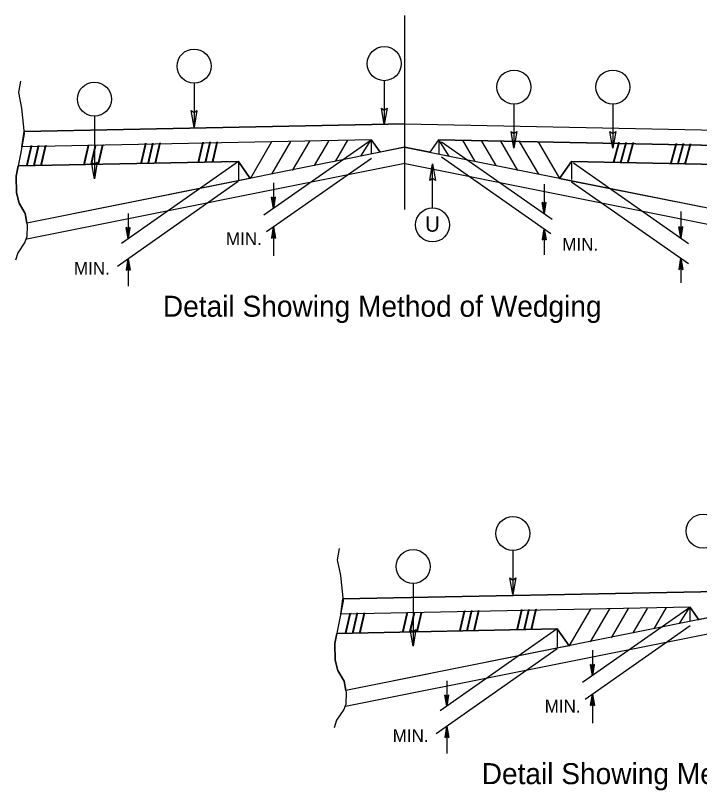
# Model space of a CAD drawing. Extents: x 1818040 to 1825768, y 638918 to 648046.
# Drawn here: x 1824035 to 1824618, y 640342 to 641002 of the extents above; entities that cross this region are included whole.
import ezdxf

# ---------------------------------------------------------------- set-up
doc = ezdxf.new("R2010")
doc.units = 0
for name, color, linetype in [('Typical Detail Wedge2 CELL', 7, 'Continuous'), ('Typical ID Circle CELL', 7, 'Continuous'), ('Typical Terminator CELL', 7, 'Continuous'), ('Typical Text General CELL', 7, 'Continuous'), ('Typical Text ID Circle CELL', 7, 'Continuous')]:
    doc.layers.add(name, color=color, linetype=linetype)

msp = doc.modelspace()

# ---------------------------------------------------------------- linework, layer by layer
at = {"layer": 'Typical Detail Wedge2 CELL'}
for p, q in [((1824367.23, 640836.88), (1824367.23, 641002.31)), ((1824367.23, 640836.88), (1824367.23, 640949.86)), ((1824367.22, 640909.96), (1824042.56, 640903.48)), ((1824042.56, 640903.48), (1824367.22, 640909.96)), ((1824367.22, 640909.96), (1824691.9, 640903.48)), ((1824367.25, 640909.96), (1824691.9, 640903.48)), ((1824040.71, 640890.43), (1824042.56, 640903.48)), ((1824338.74, 640896.39), (1824040.71, 640890.43)), ((1824338.74, 640896.39), (1824040.71, 640890.43)), ((1824253.59, 640894.68), (1824235.14, 640863.07)), ((1824338.37, 640896.15), (1824246.9, 640832.08)), ((1824269.79, 640895.02), (1824253.46, 640866.98)), ((1824285.83, 640895.33), (1824271.17, 640870.2)), ((1824301.99, 640895.29), (1824289.84, 640874.49)), ((1824318.28, 640896.13), (1824307.7, 640877.97)), ((1824329.51, 640882.51), (1824338.32, 640896.27)), ((1824338.32, 640896.27), (1824338.32, 640884.96)), ((1824346.03, 640885.7), (1824338.74, 640896.39)), ((1824338.74, 640896.04), (1824346.03, 640885.7)), ((1824395.95, 640896.39), (1824388.42, 640885.7)), ((1824395.95, 640896.39), (1824388.42, 640885.7)), ((1824395.47, 640896.15), (1824395.93, 640896.13)), ((1824395.95, 640896.39), (1824693.76, 640890.43)), ((1824693.76, 640890.43), (1824395.95, 640896.39)), ((1824404.95, 640882.51), (1824396.14, 640896.27)), ((1824396.14, 640896.27), (1824396.14, 640883.81)), ((1824398.43, 640894.66), (1824492.67, 640828.66)), ((1824416.17, 640896.13), (1824426.76, 640877.97)), ((1824432.46, 640895.29), (1824444.61, 640874.49)), ((1824448.62, 640895.33), (1824463.29, 640870.2)), ((1824464.66, 640895.02), (1824481, 640866.98)), ((1824480.88, 640894.68), (1824499.05, 640863.53)), ((1824367.71, 640890), (1824044.99, 640825.45)), ((1824366.74, 640890), (1824346.03, 640885.7)), ((1824366.74, 640890), (1824689.47, 640825.45)), ((1824388.42, 640885.7), (1824366.74, 640890)), ((1824338.58, 640880.49), (1824249.07, 640817.82)), ((1824398.3, 640881.83), (1824491.62, 640816.49)), ((1824225.2, 640877.84), (1824037.55, 640874.08)), ((1824037.55, 640874.08), (1824225.2, 640877.84)), ((1824367.1, 640876.11), (1824044.89, 640811.66)), ((1824225.2, 640877.84), (1824125.56, 640808.07)), ((1824235.4, 640863.5), (1824225.2, 640877.84)), ((1824225.2, 640877.84), (1824225.2, 640861.47)), ((1824225.2, 640877.84), (1824235.38, 640863.53)), ((1824367.35, 640876.11), (1824690.31, 640811.51)), ((1824509.25, 640877.84), (1824499.05, 640863.53)), ((1824499.07, 640863.53), (1824509.25, 640877.84)), ((1824509.25, 640877.84), (1824696.91, 640874.08)), ((1824509.25, 640877.84), (1824509.25, 640862.62)), ((1824643.09, 640875.16), (1824509.25, 640877.84)), ((1824510.77, 640876.78), (1824609.04, 640807.96)), ((1824225.11, 640860.95), (1824122.11, 640788.47)), ((1824225.2, 640861.49), (1824192.52, 640854.95)), ((1824235.38, 640863.53), (1824225.2, 640861.49)), ((1824499.05, 640863.53), (1824541.94, 640854.95)), ((1824509.25, 640860.64), (1824608.88, 640790.86)), ((1824192.52, 640854.95), (1824044.99, 640825.45)), ((1824255.23, 640859.69), (1824255.23, 640837.93)), ((1824485.79, 640858.44), (1824485.79, 640833.49)), ((1824541.94, 640854.95), (1824689.47, 640825.45)), ((1824255.23, 640837.93), (1824253.54, 640847.47)), ((1824255.23, 640846.23), (1824253.54, 640847.47)), ((1824255.23, 640837.93), (1824253.78, 640847.29)), ((1824254.02, 640847.11), (1824255.23, 640837.93)), ((1824255.23, 640837.93), (1824256.92, 640847.47)), ((1824256.92, 640847.47), (1824255.23, 640846.23)), ((1824256.68, 640847.29), (1824255.23, 640837.93)), ((1824255.23, 640837.93), (1824256.42, 640847.11)), ((1824255.23, 640837.93), (1824254.26, 640846.94)), ((1824254.51, 640846.76), (1824255.23, 640837.93)), ((1824255.23, 640837.93), (1824254.75, 640846.58)), ((1824254.99, 640846.4), (1824255.23, 640837.93)), ((1824256.18, 640846.94), (1824255.23, 640837.93)), ((1824255.23, 640837.93), (1824255.94, 640846.76)), ((1824255.7, 640846.58), (1824255.23, 640837.93)), ((1824255.23, 640837.93), (1824255.46, 640846.4)), ((1824255.23, 640846.23), (1824255.23, 640837.93)), ((1824485.79, 640833.49), (1824484.1, 640843.04)), ((1824485.79, 640841.8), (1824484.1, 640843.04)), ((1824485.79, 640833.49), (1824484.34, 640842.86)), ((1824484.58, 640842.68), (1824485.79, 640833.49)), ((1824485.79, 640833.49), (1824484.82, 640842.5)), ((1824485.06, 640842.32), (1824485.79, 640833.49)), ((1824485.79, 640833.49), (1824485.3, 640842.16)), ((1824485.54, 640841.98), (1824485.79, 640833.49)), ((1824485.79, 640833.49), (1824487.47, 640843.04)), ((1824487.47, 640843.04), (1824485.79, 640841.8)), ((1824487.22, 640842.86), (1824485.79, 640833.49)), ((1824485.79, 640833.49), (1824486.98, 640842.68)), ((1824486.74, 640842.5), (1824485.79, 640833.49)), ((1824485.79, 640833.49), (1824486.5, 640842.32)), ((1824486.26, 640842.16), (1824485.79, 640833.49)), ((1824485.79, 640833.49), (1824486.02, 640841.98)), ((1824485.79, 640841.8), (1824485.79, 640833.49)), ((1824602.29, 640835.26), (1824602.29, 640812.7)), ((1824131.17, 640833.68), (1824131.17, 640811.98)), ((1824131.17, 640811.98), (1824129.47, 640821.53)), ((1824131.17, 640820.3), (1824129.47, 640821.53)), ((1824131.17, 640811.98), (1824129.71, 640821.36)), ((1824129.97, 640821.17), (1824131.17, 640811.98)), ((1824131.17, 640811.98), (1824130.21, 640821.01)), ((1824130.45, 640820.84), (1824131.17, 640811.98)), ((1824131.17, 640811.98), (1824132.85, 640821.53)), ((1824132.85, 640821.53), (1824131.17, 640820.3)), ((1824132.61, 640821.36), (1824131.17, 640811.98)), ((1824131.17, 640811.98), (1824132.37, 640821.17)), ((1824132.13, 640821.01), (1824131.17, 640811.98)), ((1824131.17, 640811.98), (1824131.88, 640820.84)), ((1824255.23, 640822.13), (1824253.54, 640812.58)), ((1824253.78, 640812.77), (1824255.23, 640822.13)), ((1824255.23, 640822.13), (1824254.02, 640812.94)), ((1824254.26, 640813.13), (1824255.23, 640822.13)), ((1824255.23, 640822.13), (1824254.51, 640813.3)), ((1824254.75, 640813.46), (1824255.23, 640822.13)), ((1824255.23, 640822.13), (1824254.99, 640813.64)), ((1824255.23, 640822.13), (1824255.23, 640797.62)), ((1824255.23, 640822.13), (1824256.92, 640812.58)), ((1824255.23, 640813.82), (1824255.23, 640822.13)), ((1824255.46, 640813.64), (1824255.23, 640822.13)), ((1824255.23, 640822.13), (1824255.7, 640813.46)), ((1824255.94, 640813.3), (1824255.23, 640822.13)), ((1824255.23, 640822.13), (1824256.18, 640813.13)), ((1824256.42, 640812.94), (1824255.23, 640822.13)), ((1824255.23, 640822.13), (1824256.68, 640812.77)), ((1824602.29, 640812.7), (1824600.61, 640822.24)), ((1824602.29, 640821.01), (1824600.61, 640822.24)), ((1824602.29, 640812.7), (1824600.85, 640822.06)), ((1824601.08, 640821.89), (1824602.29, 640812.7)), ((1824602.29, 640812.7), (1824601.32, 640821.72)), ((1824601.56, 640821.53), (1824602.29, 640812.7)), ((1824602.29, 640812.7), (1824601.8, 640821.36)), ((1824602.04, 640821.17), (1824602.29, 640812.7)), ((1824602.29, 640812.7), (1824603.97, 640822.24)), ((1824603.97, 640822.24), (1824602.29, 640821.01)), ((1824603.72, 640822.06), (1824602.29, 640812.7)), ((1824602.29, 640812.7), (1824603.48, 640821.89)), ((1824603.24, 640821.72), (1824602.29, 640812.7)), ((1824602.29, 640812.7), (1824603.01, 640821.53)), ((1824602.77, 640821.36), (1824602.29, 640812.7)), ((1824602.29, 640812.7), (1824602.53, 640821.17)), ((1824602.29, 640821.01), (1824602.29, 640812.7)), ((1824131.17, 640811.98), (1824130.69, 640820.66)), ((1824130.93, 640820.48), (1824131.17, 640811.98)), ((1824131.66, 640820.66), (1824131.17, 640811.98)), ((1824131.17, 640811.98), (1824131.41, 640820.48)), ((1824131.17, 640820.3), (1824131.17, 640811.98)), ((1824485.79, 640820.58), (1824484.1, 640811.03)), ((1824484.34, 640811.22), (1824485.79, 640820.58)), ((1824485.79, 640820.58), (1824484.58, 640811.39)), ((1824484.82, 640811.58), (1824485.79, 640820.58)), ((1824485.79, 640820.58), (1824485.06, 640811.74)), ((1824485.3, 640811.91), (1824485.79, 640820.58)), ((1824485.79, 640820.58), (1824485.54, 640812.09)), ((1824485.79, 640820.58), (1824485.79, 640798.26)), ((1824485.79, 640820.58), (1824487.47, 640811.03)), ((1824485.79, 640812.27), (1824485.79, 640820.58)), ((1824486.02, 640812.09), (1824485.79, 640820.58)), ((1824485.79, 640820.58), (1824486.26, 640811.91)), ((1824486.5, 640811.74), (1824485.79, 640820.58)), ((1824485.79, 640820.58), (1824486.74, 640811.58)), ((1824486.98, 640811.39), (1824485.79, 640820.58)), ((1824485.79, 640820.58), (1824487.22, 640811.22)), ((1824253.54, 640812.58), (1824255.23, 640813.82)), ((1824255.23, 640813.82), (1824256.92, 640812.58)), ((1824484.1, 640811.03), (1824485.79, 640812.27)), ((1824485.79, 640812.27), (1824487.47, 640811.03)), ((1824131.17, 640794.82), (1824129.47, 640785.27)), ((1824129.74, 640785.45), (1824131.17, 640794.82)), ((1824131.17, 640794.82), (1824129.97, 640785.63)), ((1824130.21, 640785.81), (1824131.17, 640794.82)), ((1824131.17, 640794.82), (1824130.45, 640785.99)), ((1824130.69, 640786.15), (1824131.17, 640794.82)), ((1824131.17, 640794.82), (1824130.93, 640786.32)), ((1824131.17, 640794.82), (1824131.17, 640771.62)), ((1824131.17, 640794.82), (1824132.85, 640785.27)), ((1824131.17, 640786.51), (1824131.17, 640794.82)), ((1824131.41, 640786.32), (1824131.17, 640794.82)), ((1824131.17, 640794.82), (1824131.66, 640786.15)), ((1824131.9, 640785.99), (1824131.17, 640794.82)), ((1824131.17, 640794.82), (1824132.13, 640785.81)), ((1824132.37, 640785.63), (1824131.17, 640794.82)), ((1824131.17, 640794.82), (1824132.61, 640785.45)), ((1824602.29, 640795.49), (1824600.61, 640785.94)), ((1824600.85, 640786.12), (1824602.29, 640795.49)), ((1824602.29, 640795.49), (1824601.08, 640786.3)), ((1824601.32, 640786.48), (1824602.29, 640795.49)), ((1824602.29, 640795.49), (1824601.56, 640786.65)), ((1824601.8, 640786.83), (1824602.29, 640795.49)), ((1824602.29, 640795.49), (1824602.04, 640787)), ((1824602.29, 640795.49), (1824602.29, 640774.53)), ((1824602.29, 640795.49), (1824603.97, 640785.94)), ((1824602.29, 640787.19), (1824602.29, 640795.49)), ((1824602.53, 640787), (1824602.29, 640795.49)), ((1824602.29, 640795.49), (1824602.77, 640786.83)), ((1824603.01, 640786.65), (1824602.29, 640795.49)), ((1824602.29, 640795.49), (1824603.24, 640786.48)), ((1824603.48, 640786.3), (1824602.29, 640795.49)), ((1824602.29, 640795.49), (1824603.72, 640786.12)), ((1824129.47, 640785.27), (1824131.17, 640786.51)), ((1824131.17, 640786.51), (1824132.85, 640785.27)), ((1824600.61, 640785.94), (1824602.29, 640787.19)), ((1824602.29, 640787.19), (1824603.97, 640785.94)), ((1824638.96, 640511.63), (1824314.3, 640505.15)), ((1824314.3, 640505.15), (1824638.96, 640511.63)), ((1824312.45, 640492.11), (1824314.3, 640505.15)), ((1824610.48, 640498.06), (1824312.45, 640492.11)), ((1824610.48, 640498.06), (1824312.45, 640492.11)), ((1824610.11, 640497.82), (1824518.64, 640433.75)), ((1824590.03, 640497.8), (1824579.44, 640479.64)), ((1824601.26, 640484.18), (1824610.07, 640497.94)), ((1824610.07, 640497.94), (1824610.07, 640486.63)), ((1824617.78, 640487.37), (1824610.48, 640498.06)), ((1824610.48, 640497.71), (1824617.78, 640487.37)), ((1824639.45, 640491.68), (1824316.74, 640427.12)), ((1824525.33, 640496.35), (1824506.88, 640464.74)), ((1824541.53, 640496.69), (1824525.2, 640468.65)), ((1824557.57, 640497), (1824542.92, 640471.87)), ((1824573.73, 640496.96), (1824561.58, 640476.16)), ((1824638.48, 640491.68), (1824617.78, 640487.37)), ((1824496.94, 640479.51), (1824309.29, 640475.75)), ((1824309.29, 640475.75), (1824496.94, 640479.51)), ((1824638.84, 640477.78), (1824316.63, 640413.33)), ((1824496.94, 640479.51), (1824397.3, 640409.74)), ((1824507.14, 640465.17), (1824496.94, 640479.51)), ((1824496.94, 640479.51), (1824496.94, 640463.14)), ((1824496.94, 640479.51), (1824507.12, 640465.2)), ((1824610.33, 640482.16), (1824520.81, 640419.49)), ((1824507.12, 640465.2), (1824496.94, 640463.16)), ((1824496.86, 640462.62), (1824393.85, 640390.14)), ((1824496.94, 640463.16), (1824464.26, 640456.62)), ((1824526.97, 640461.36), (1824526.97, 640439.6)), ((1824464.26, 640456.62), (1824316.74, 640427.12)), ((1824526.97, 640439.6), (1824525.29, 640449.14)), ((1824526.97, 640447.9), (1824525.29, 640449.14)), ((1824526.97, 640439.6), (1824525.53, 640448.96)), ((1824525.76, 640448.78), (1824526.97, 640439.6)), ((1824526.97, 640439.6), (1824526, 640448.61)), ((1824526.25, 640448.43), (1824526.97, 640439.6)), ((1824526.97, 640439.6), (1824526.49, 640448.25)), ((1824526.73, 640448.07), (1824526.97, 640439.6)), ((1824526.97, 640439.6), (1824528.66, 640449.14)), ((1824528.66, 640449.14), (1824526.97, 640447.9)), ((1824528.43, 640448.96), (1824526.97, 640439.6)), ((1824526.97, 640439.6), (1824528.16, 640448.78)), ((1824527.92, 640448.61), (1824526.97, 640439.6)), ((1824526.97, 640439.6), (1824527.69, 640448.43)), ((1824527.45, 640448.25), (1824526.97, 640439.6)), ((1824526.97, 640439.6), (1824527.21, 640448.07)), ((1824526.97, 640447.9), (1824526.97, 640439.6)), ((1824402.91, 640435.35), (1824402.91, 640413.65)), ((1824402.91, 640413.65), (1824401.22, 640423.2)), ((1824402.91, 640421.97), (1824401.22, 640423.2)), ((1824402.91, 640413.65), (1824401.46, 640423.03)), ((1824401.72, 640422.84), (1824402.91, 640413.65)), ((1824402.91, 640413.65), (1824401.96, 640422.68)), ((1824402.19, 640422.51), (1824402.91, 640413.65)), ((1824402.91, 640413.65), (1824402.43, 640422.33)), ((1824402.67, 640422.15), (1824402.91, 640413.65)), ((1824402.91, 640413.65), (1824404.59, 640423.2)), ((1824404.59, 640423.2), (1824402.91, 640421.97)), ((1824404.36, 640423.03), (1824402.91, 640413.65)), ((1824402.91, 640413.65), (1824404.12, 640422.84)), ((1824403.88, 640422.68), (1824402.91, 640413.65)), ((1824402.91, 640413.65), (1824403.63, 640422.51)), ((1824403.4, 640422.33), (1824402.91, 640413.65)), ((1824402.91, 640413.65), (1824403.15, 640422.15)), ((1824402.91, 640421.97), (1824402.91, 640413.65)), ((1824526.97, 640423.8), (1824525.29, 640414.25)), ((1824525.53, 640414.44), (1824526.97, 640423.8)), ((1824526.97, 640423.8), (1824525.76, 640414.61)), ((1824526, 640414.8), (1824526.97, 640423.8)), ((1824526.97, 640423.8), (1824526.25, 640414.97)), ((1824526.49, 640415.13), (1824526.97, 640423.8)), ((1824526.97, 640423.8), (1824526.73, 640415.31)), ((1824526.97, 640423.8), (1824526.97, 640399.29)), ((1824526.97, 640423.8), (1824528.66, 640414.25)), ((1824526.97, 640415.49), (1824526.97, 640423.8)), ((1824527.21, 640415.31), (1824526.97, 640423.8)), ((1824526.97, 640423.8), (1824527.45, 640415.13)), ((1824527.69, 640414.97), (1824526.97, 640423.8)), ((1824526.97, 640423.8), (1824527.92, 640414.8)), ((1824528.16, 640414.61), (1824526.97, 640423.8)), ((1824526.97, 640423.8), (1824528.43, 640414.44)), ((1824525.29, 640414.25), (1824526.97, 640415.49)), ((1824526.97, 640415.49), (1824528.66, 640414.25)), ((1824402.91, 640396.49), (1824401.22, 640386.94)), ((1824401.48, 640387.12), (1824402.91, 640396.49)), ((1824402.91, 640396.49), (1824401.72, 640387.3)), ((1824401.96, 640387.48), (1824402.91, 640396.49)), ((1824402.91, 640396.49), (1824402.19, 640387.66)), ((1824402.43, 640387.82), (1824402.91, 640396.49)), ((1824402.91, 640396.49), (1824402.67, 640387.99)), ((1824402.91, 640396.49), (1824402.91, 640373.29)), ((1824402.91, 640396.49), (1824404.59, 640386.94)), ((1824402.91, 640388.18), (1824402.91, 640396.49)), ((1824403.15, 640387.99), (1824402.91, 640396.49)), ((1824402.91, 640396.49), (1824403.4, 640387.82)), ((1824403.64, 640387.66), (1824402.91, 640396.49)), ((1824402.91, 640396.49), (1824403.88, 640387.48)), ((1824404.12, 640387.3), (1824402.91, 640396.49)), ((1824402.91, 640396.49), (1824404.36, 640387.12)), ((1824401.22, 640386.94), (1824402.91, 640388.18)), ((1824402.91, 640388.18), (1824404.59, 640386.94))]:
    msp.add_line(p, q, dxfattribs=at)
for points in [[(1824039.54, 640946.33), (1824037.81, 640936.82), (1824040.41, 640923.29), (1824042.7, 640901.4), (1824039.54, 640884.12), (1824035.8, 640865.41), (1824036.09, 640851.29), (1824038.39, 640842.37), (1824043.58, 640833.43), (1824045.3, 640823.64), (1824045.02, 640813.86), (1824043.29, 640809.24), (1824037.25, 640800.02), (1824035.23, 640793.68)], [(1824044.98, 640825.45), (1824043.58, 640833.43), (1824038.39, 640842.37), (1824036.09, 640851.29), (1824035.8, 640865.41), (1824037.53, 640874.08)], [(1824311.28, 640548), (1824309.55, 640538.49), (1824312.15, 640524.96), (1824314.44, 640503.07), (1824311.28, 640485.79), (1824307.55, 640467.08), (1824307.83, 640452.96), (1824310.14, 640444.04), (1824315.33, 640435.1), (1824317.05, 640425.31), (1824316.76, 640415.53), (1824315.03, 640410.91), (1824308.99, 640401.69), (1824306.97, 640395.35)], [(1824316.72, 640427.12), (1824315.33, 640435.1), (1824310.14, 640444.04), (1824307.83, 640452.96), (1824307.55, 640467.08), (1824309.28, 640475.75)]]:
    msp.add_lwpolyline(points, dxfattribs=at)
at = {"layer": 'Typical ID Circle CELL'}
for p, q in [((1824349.6, 640946.77), (1824349.6, 640909.29)), ((1824187.46, 640944.68), (1824187.46, 640907.2)), ((1824460.14, 640926.85), (1824460.14, 640889.37)), ((1824544.49, 640926.85), (1824544.49, 640889.37)), ((1824102.46, 640916.53), (1824102.46, 640863.23)), ((1824390.72, 640838.31), (1824390.72, 640875.79)), ((1824459.2, 640546.35), (1824459.2, 640508.87)), ((1824374.21, 640518.2), (1824374.21, 640464.9))]:
    msp.add_line(p, q, dxfattribs=at)
for centre in [(1824187.46, 640959.18), (1824349.6, 640961.27), (1824460.14, 640941.35), (1824544.48, 640941.35), (1824102.46, 640931.02), (1824390.72, 640823.81), (1824621.34, 640562.94), (1824459.2, 640560.85), (1824374.2, 640532.69)]:
    msp.add_circle(centre, 14.5, dxfattribs=at)
at = {"layer": 'Typical Terminator CELL'}
for points in [[(1824189.88, 640921.26), (1824187.46, 640907.2), (1824184.96, 640921.34), (1824187.46, 640919.55)], [(1824189.88, 640921.26), (1824187.46, 640907.2), (1824184.96, 640921.34), (1824187.46, 640919.55)], [(1824352.02, 640923.35), (1824349.6, 640909.29), (1824347.1, 640923.43), (1824349.6, 640921.63)], [(1824352.02, 640923.35), (1824349.6, 640909.29), (1824347.1, 640923.43), (1824349.6, 640921.63)], [(1824462.56, 640903.43), (1824460.14, 640889.37), (1824457.64, 640903.51), (1824460.14, 640901.71)], [(1824462.56, 640903.43), (1824460.14, 640889.37), (1824457.64, 640903.51), (1824460.14, 640901.71)], [(1824546.91, 640903.43), (1824544.49, 640889.37), (1824541.99, 640903.51), (1824544.49, 640901.71)], [(1824546.91, 640903.43), (1824544.49, 640889.37), (1824541.99, 640903.51), (1824544.49, 640901.71)], [(1824104.88, 640877.29), (1824102.46, 640863.23), (1824099.96, 640877.37), (1824102.46, 640875.58)], [(1824104.88, 640877.29), (1824102.46, 640863.23), (1824099.96, 640877.37), (1824102.46, 640875.58)], [(1824388.3, 640861.73), (1824390.72, 640875.79), (1824393.22, 640861.65), (1824390.72, 640863.45)], [(1824388.3, 640861.73), (1824390.72, 640875.79), (1824393.22, 640861.65), (1824390.72, 640863.45)], [(1824461.62, 640522.93), (1824459.2, 640508.87), (1824456.7, 640523.01), (1824459.2, 640521.22)], [(1824461.62, 640522.93), (1824459.2, 640508.87), (1824456.7, 640523.01), (1824459.2, 640521.22)], [(1824376.63, 640478.96), (1824374.21, 640464.9), (1824371.71, 640479.04), (1824374.21, 640477.25)], [(1824376.63, 640478.96), (1824374.21, 640464.9), (1824371.71, 640479.04), (1824374.21, 640477.25)]]:
    msp.add_lwpolyline(points, close=True, dxfattribs=at)

# ---------------------------------------------------------------- texts
at = {"layer": 'Typical Detail Wedge2 CELL'}
for height, rotation, p in [(16.275, 1.14453, (1824141.43, 640876.32)), (16.276, 1.14629, (1824190.25, 640877.32)), (16.276, 358.85527, (1824544.21, 640877.32)), (16.275, 358.85361, (1824593.03, 640876.32)), (16.281, 1.14473, (1824044, 640874.31)), (16.281, 1.14639, (1824092.66, 640874.88)), (16.281, 1.14473, (1824315.75, 640475.98)), (16.281, 1.14639, (1824364.41, 640476.55)), (16.275, 1.14453, (1824413.18, 640477.99)), (16.276, 1.14629, (1824461.99, 640478.99))]:
    msp.add_text('/// ', height=height, rotation=rotation, dxfattribs=at).set_placement(p)
for p in [(1824214.62, 640806.62), (1824501.28, 640801.91), (1824085.04, 640781.47), (1824486.36, 640408.29), (1824356.78, 640383.15)]:
    msp.add_text('MIN.', height=10.846, dxfattribs=at).set_placement(p)
at = {"layer": 'Typical Text General CELL'}
for p in [(1824160.88, 640745.56), (1824432.62, 640347.23)]:
    msp.add_text('Detail Showing Method of Wedging', height=17.9034, dxfattribs=at).set_placement(p)
at = {"layer": 'Typical Text ID Circle CELL'}
msp.add_text('U', height=12.98, dxfattribs=at).set_placement((1824384.38, 640818.07))

doc.saveas('drawing.dxf')
